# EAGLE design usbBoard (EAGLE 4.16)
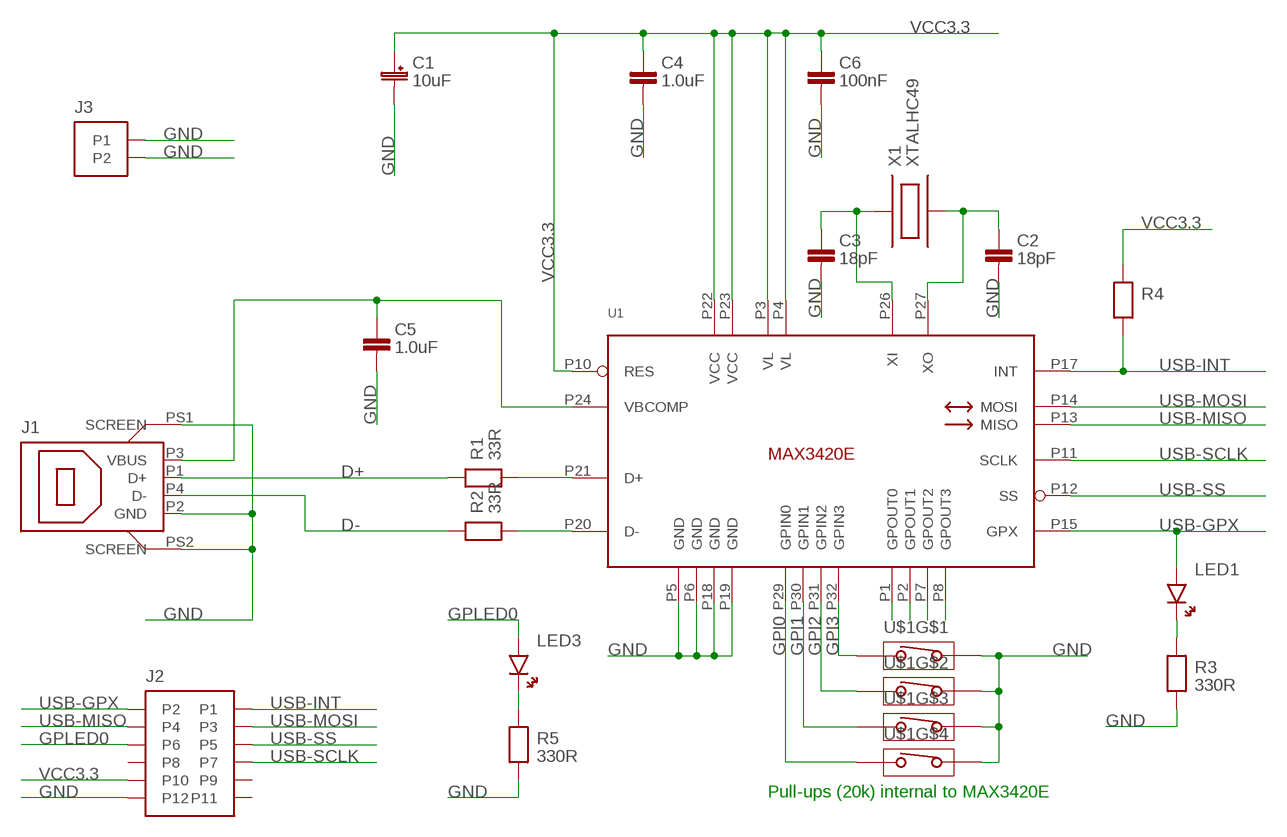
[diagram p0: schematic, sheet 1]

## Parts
C1  10uF  CAP-POL2.0-5.0  [2.0-5.0POL]
C2  18pF  CAP0805  [0805]
C3  18pF  CAP0805  [0805]
C4  1.0uF  CAP0805  [0805]
C5  1.0uF  CAP0805  [0805]
C6  100nF  CAP0805  [0805]
J1  USB-B  [USB-B]
J2  2X6-HEADER0.1INRA  [2X6-0.1IN-RA-HEADER]
J3  1X2-HEADER0.1IN  [1X2-0.1IN-HEADER]
LED1  LEDKINGBRIGHT-3.2X1.6  [3.2X1.6]
LED3  LEDKINGBRIGHT-3.2X1.6  [3.2X1.6]
R1  33R  RES0805  [0805]
R2  33R  RES0805  [0805]
R3  330R  RES0805  [0805]
R4  RES0805  [0805]
R5  330R  RES0805  [0805]
U1  MAX3420ELQFP32  [LQFP32]
U$1  4-SPSTSMD  [DIL4]
X1  XTALHC49  [HC49]

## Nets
D+: J1.P1(D+) R1.P1
D-: J1.P4(D-) R2.P1
GND: C1.P- C2.P2 C3.P2 C4.P2 C5.P2 C6.P2 J1.P2(GND) J1.PS1(SCREEN) J1.PS2(SCREEN) J2.P12 J3.P1 J3.P2 R3.P2 R5.P2 U1.P5(GND) U1.P6(GND) U1.P18(GND) U1.P19(GND) U$1.P$5(P2) U$1.P$6(P2) U$1.P$7(P2) U$1.P$8(P2)
GPI0: U1.P29(GPIN0) U$1.P$4(P1)
GPI1: U1.P30(GPIN1) U$1.P$3(P1)
GPI2: U1.P31(GPIN2) U$1.P$2(P1)
GPI3: U1.P32(GPIN3) U$1.P$1(P1)
GPLED0: J2.P6 LED3.PA
N$3: R1.P2 U1.P21(D+)
N$4: U1.P8(GPOUT3)
N$5: R2.P2 U1.P20(D-)
N$6: U1.P7(GPOUT2)
N$7: U1.P2(GPOUT1)
N$8: C2.P1 U1.P27(XO) X1.P2
N$9: C3.P1 U1.P26(XI) X1.P1
N$11: LED3.PC R5.P1
N$14: U1.P1(GPOUT0)
N$15: LED1.PC R3.P1
USB-GPX: J2.P2 LED1.PA U1.P15(GPX)
USB-INT: J2.P1 R4.P2 U1.P17(INT)
USB-MISO: J2.P4 U1.P13(MISO)
USB-MOSI: J2.P3 U1.P14(MOSI)
USB-SCLK: J2.P7 U1.P11(SCLK)
USB-SS: J2.P5 U1.P12(SS)
VBUS: C5.P1 J1.P3(VBUS) U1.P24(VBCOMP)
VCC3.3: C1.P+ C4.P1 C6.P1 J2.P10 R4.P1 U1.P3(VL) U1.P4(VL) U1.P10(RES) U1.P22(VCC) U1.P23(VCC)
Unconnected: J2.P8 J2.P9 J2.P11

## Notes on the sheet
- Pull-ups (20k) internal to MAX3420E

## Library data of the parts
C1 = passive:CAP-POL
C2-C6 = passive:CAP
J1 = connectors:USB-B
J2 = connectors:2X6-HEADER
J3 = connectors:1X2-HEADER
LED1 LED3 = leds:LED
R1-R5 = passive:RES
U1 = active:MAX3420E
U$1 = switches:4-SPST
X1 = passive:XTAL

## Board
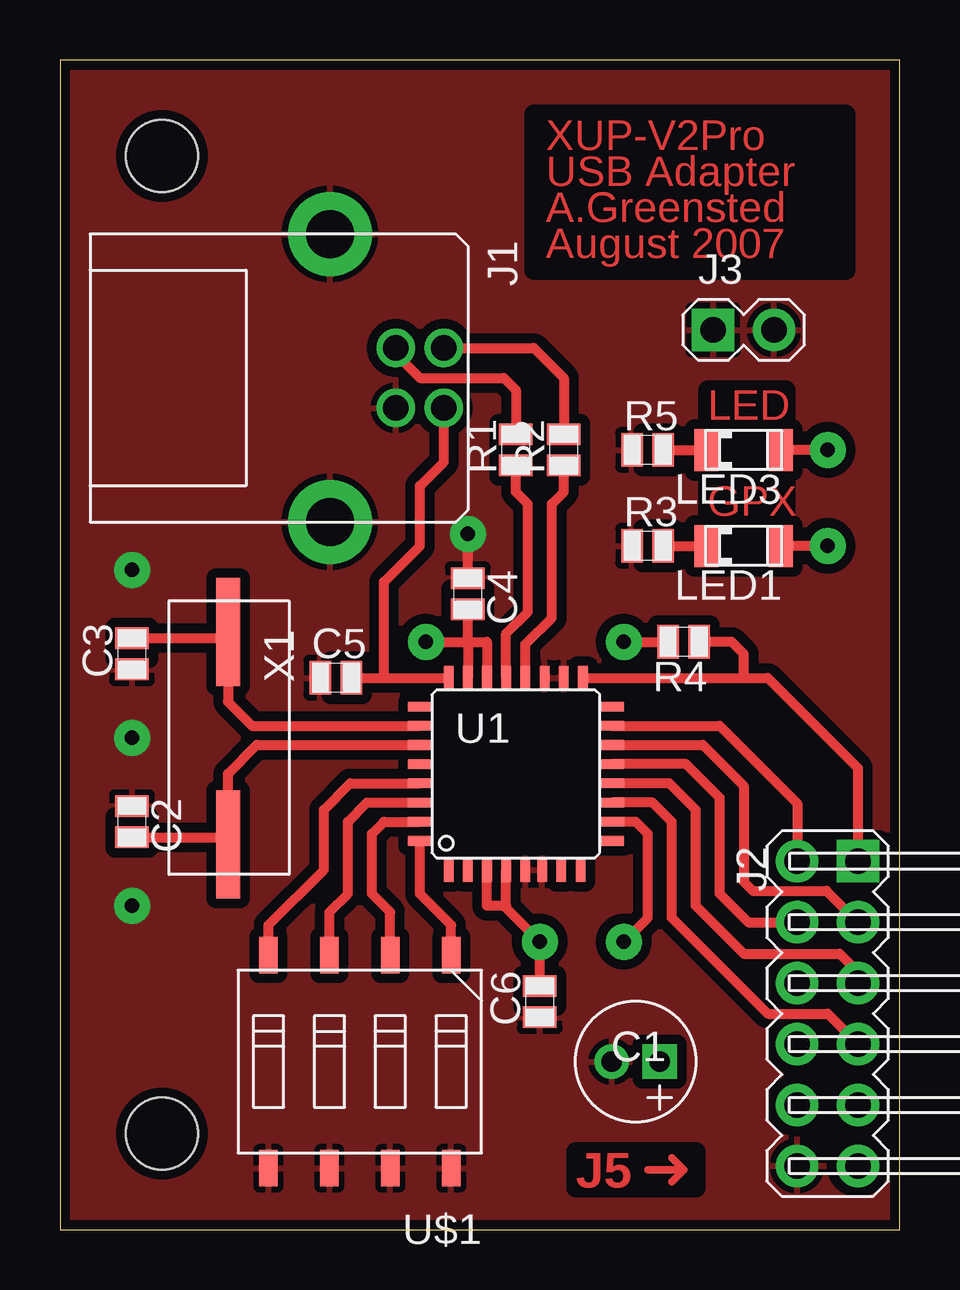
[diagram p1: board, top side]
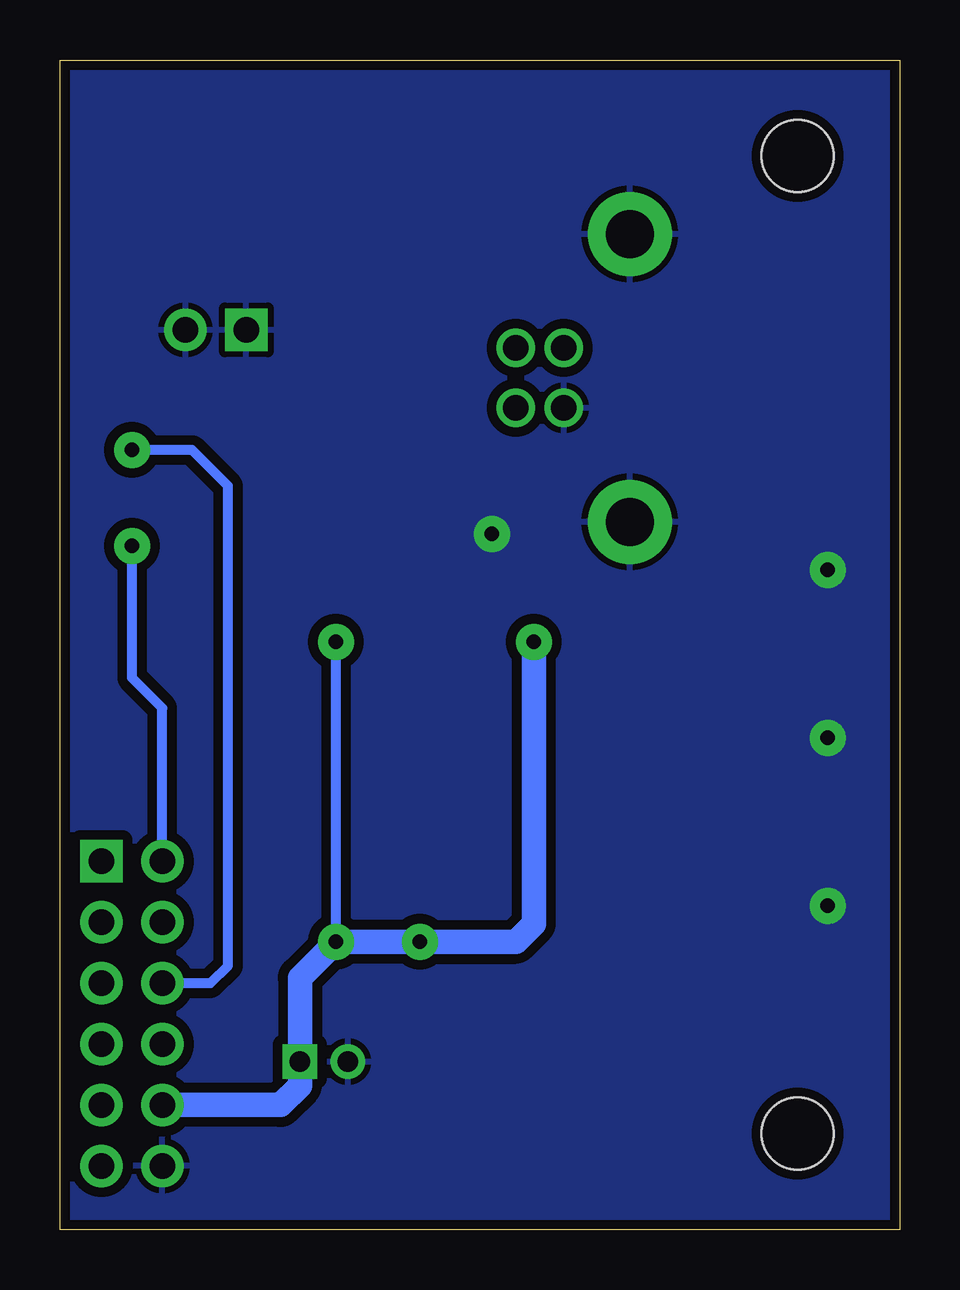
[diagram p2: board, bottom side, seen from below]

Size 35 x 48.75 mm. Coordinates in mm from the lower left corner, seen from the top.
Outline: 0,0 35,0 35,48.75 0,48.75 0,0
Copper layers (1*16): Top 0.035mm / dielectric 1.5mm / Bottom 0.035mm
Design rules "default": minimum track width 10mil, minimum drill 24mil, track to track 8mil, track to pad 8mil, pad to pad 8mil, via to via 8mil, smd to smd 8mil, copper to edge 10mil, drill to drill 8mil, minimum pad ring 10mil, minimum via ring 8mil, stop-mask expansion 4mil, vias tented up to drill 0mil, thermal gap 10mil
Holes 3 mm at 4.25,4 4.25,44.75
tRestrict: area 16,16 to 22,22; area 19.8,40 to 32.8,46.5; area 21.5,1.8 to 26.5,3.2; area 27,29.8 to 30.2,31; area 27,33.8 to 30.2,35

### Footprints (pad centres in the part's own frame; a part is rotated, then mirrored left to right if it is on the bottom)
2.0-5.0POL = drill 0.85 pad 1.422 square: P+ -1,0 | drill 0.85 pad 1.422 round: P- 1,0
0805 = smd 1.4 x 0.9: P1 0,0.65; P2 0,-0.65
USB-B = drill 1.05 pad 1.6 round: P1 -1.25,0; P2 1.25,0; P3 1.25,2; P4 -1.25,2 | drill 2 pad 3.5 round: PS1 -6,-2.75; PS2 6,-2.75
2X6-0.1IN-RA-HEADER = drill 1.05 pad 1.778 square: P1 -6.35,1.27 | drill 1.05 pad 1.778 round: P2 -6.35,-1.27; P3 -3.81,1.27; P4 -3.81,-1.27; P5 -1.27,1.27; P6 -1.27,-1.27; P7 1.27,1.27; P8 1.27,-1.27; P9 3.81,1.27; P10 3.81,-1.27; P11 6.35,1.27; P12 6.35,-1.27
1X2-0.1IN-HEADER = drill 1.05 pad 1.778 square: P1 -1.27,0 | drill 1.05 pad 1.778 round: P2 1.27,0
3.2X1.6 = smd 1 x 1.75: PA -1.55,0; PC 1.55,0
LQFP32 = smd 0.4 x 1: P1 -2.8,-4; P2 -2,-4; P3 -1.2,-4; P4 -0.4,-4; P5 0.4,-4; P6 1.1,-4; P7 1.9,-4; P8 2.7,-4; P17 2.8,4; P18 2,4; P19 1.2,4; P20 0.4,4; P21 -0.4,4; P22 -1.2,4; P23 -2,4; P24 -2.8,4 | smd 1 x 0.4: P9 4,-2.8; P10 4,-2; P11 4,-1.2; P12 4,-0.4; P13 4,0.4; P14 4,1.2; P15 4,2; P16 4,2.8; P25 -4,2.8; P26 -4,2; P27 -4,1.2; P28 -4,0.4; P29 -4,-0.4; P30 -4,-1.2; P31 -4,-2; P32 -4,-2.8
DIL4 = smd 0.762 x 1.524: P$1 -3.81,-4.445; P$2 -1.27,-4.445; P$3 1.27,-4.445; P$4 3.81,-4.445; P$5 3.81,4.445; P$6 1.27,4.445; P$7 -1.27,4.445; P$8 -3.81,4.445
HC49 = smd 4.5 x 1: P1 -4.4,0; P2 4.45,0

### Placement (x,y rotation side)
C1  24,7 180 top
C2  3,17 180 top
C3  3,24 0 top
C4  17,26.5 180 top
C5  11.5,23 270 top
C6  20,9.5 0 top
J1  14,35.5 270 top
J2  32,9 270 top
J3  28.5,37.5 0 top
LED1  28.5,28.5 180 top
LED3  28.5,32.5 180 top
R1  19,32.5 0 top
R2  21,32.5 0 top
R3  24.5,28.5 270 top
R4  26,24.5 90 top
R5  24.5,32.5 270 top
U1  19,19 0 top
U$1  12.5,7 180 top
X1  7,20.5 270 top

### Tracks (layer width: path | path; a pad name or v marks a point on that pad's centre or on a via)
D+
  Top 0.406: J1.P1 14,36.5 15,35.5 18.5,35.5 19,35 R1.P1
D-
  Top 0.406: J1.P4 19.75,36.75 21,35.5 R2.P1
GND  (via drill 0.6 pad 1.5)
  Top 0.406: C4.P2 v17,29
  other vias: 3,20.5 3,27.5 3,13.5
  pour Top (isolate 0.406): 0,0 0,48.75 35,48.75 35,0
  pour Bottom (isolate 0.406): 0,0 35,0 35,48.75 0,48.75
GPI0
  Top 0.406: U1.P29 12.1,18.6 11,17.5 11,15 8.69,12.69 U$1.P$4
GPI1
  Top 0.406: U1.P30 12.8,17.8 12,17 12,14 11.23,13.23 U$1.P$3
GPI2
  Top 0.406: U1.P31 13.5,17 13,16.5 13,14 13.77,13.23 U$1.P$2
GPI3
  Top 0.406: U1.P32 15,14 16.31,12.69 U$1.P$1
GPLED0  (via drill 0.6 pad 1.5)
  Top 0.406: v32,32.5 LED3.PA
  Bottom 0.406: v32,32.5 29.5,32.5 28,31 28,11 28.73,10.27 J2.P6
N$1
  Top 0.305: 24.5,2.5 26,2.5
N$2
  Top 0.305: 25.5,3 26,2.5 25.5,2
N$3
  Top 0.406: U1.P21 18.6,24.85 19.5,25.75 19.5,30.25 19,30.75 R1.P2
N$5
  Top 0.406: U1.P20 19.4,24.4 20.5,25.5 20.5,30.25 21,30.75 R2.P2
N$8
  Top 0.406: U1.P27 8.2,20.2 7,19 X1.P2 7,16 6.65,16.35 C2.P1
N$9
  Top 0.406: U1.P26 8,21 7,22 X1.P1 7,25 6.65,24.65 C3.P1
N$11
  Top 0.406: R5.P1 LED3.PC
N$15
  Top 0.406: R3.P1 LED1.PC
USB-GPX  (via drill 0.6 pad 1.5)
  Top 0.406: U1.P15 27.5,21 30.73,17.77 J2.P2 | v32,28.5 LED1.PA
  Bottom 0.406: v32,28.5 32,23 30.73,21.73 J2.P2
USB-INT
  Top 0.406: U1.P17 28.5,23 | 28.5,23 29.5,23 33.27,19.23 J2.P1 | R4.P2 28,24.5 28.5,24 28.5,23
USB-MISO
  Top 0.406: U1.P13 26.1,19.4 27.5,18 27.5,14 28.69,12.81 J2.P4
USB-MOSI
  Top 0.406: U1.P14 26.8,20.2 28.5,18.5 28.5,14.5 28.88,14.12 31.95,14.12 J2.P3
USB-SCLK
  Top 0.406: U1.P11 24.7,17.8 25.5,17 25.5,13 29.5,9 32,9 J2.P7
USB-SS
  Top 0.406: U1.P12 25.4,18.6 26.5,17.5 26.5,13.5 28.5,11.5 32.5,11.5 33.27,10.73 J2.P5
VBUS
  Top 0.406: C5.P1 13.5,23 | 13.5,23 U1.P24 | J1.P3 16,32 15,31 15,28.5 13.5,27 13.5,23
VCC3.3  (via drill 0.6 pad 1.5)
  Top 0.406: U1.P10 24,17 24.5,16.5 24.5,13 v23.5,12 | 18.6,13.5 18.6,13.4 v20,12 C6.P1 | 18.6,13.5 U1.P4 | U1.P3 17.8,13.5 18.6,13.5 | 17,24.5 U1.P23 | v15.25,24.5 17,24.5 | U1.P22 17.8,24.5 17,24.5 | 17,24.5 C4.P1 | v23.5,24.5 R4.P1
  Bottom 0.406: v23.5,12 v23.5,24.5
  Bottom 1.016: v15.25,24.5 15.25,12.75 16,12 v20,12 v23.5,12 25,10.5 C1.P+ 25,6 25.81,5.19 J2.P10

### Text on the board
Top: XUP-V2Pro | USB Adapter | A.Greensted | August 2007 | LED | GPX | J5
Reference: Grid: 0.5mm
